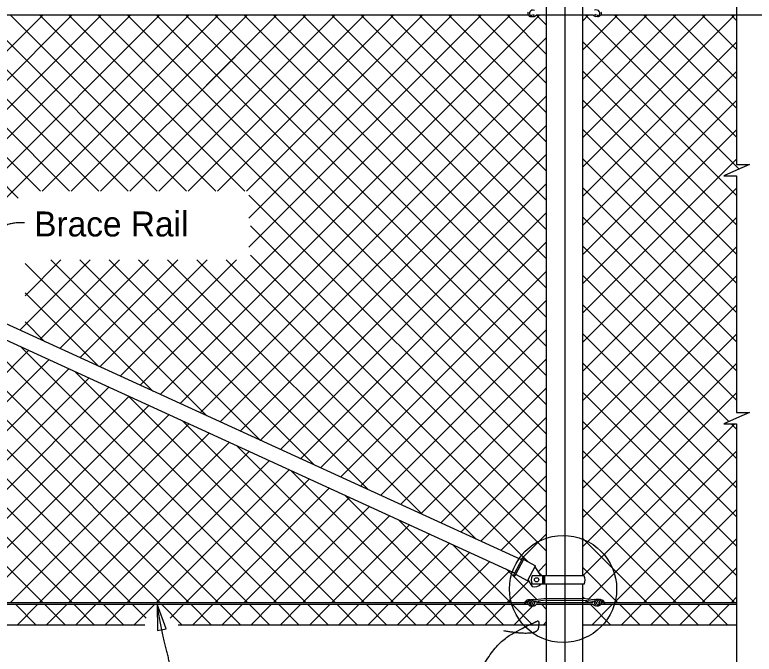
# Model space of a CAD drawing. Extents: x 0 to 41.2, y 0 to 26.
# Drawn here: x 17.77 to 23.73, y 17.23 to 22.39 of the extents above; entities that cross this region are included whole.
import ezdxf

# ---------------------------------------------------------------- set-up
doc = ezdxf.new("R2010")
doc.units = 0
for name, color, linetype in [('CL_Major', 7, 'Continuous'), ('Dimension', 7, 'Continuous'), ('Miscellaneous', 7, 'Continuous'), ('SteelMisc', 7, 'Continuous'), ('SteelMisc_h', 7, 'Continuous'), ('SupstrConc', 7, 'Continuous'), ('TextStructures', 7, 'Continuous')]:
    doc.layers.add(name, color=color, linetype=linetype)

msp = doc.modelspace()

# ---------------------------------------------------------------- linework, layer by layer
at = {"layer": 'CL_Major'}
msp.add_line((22.2062, 25.6784), (22.2062, 14.8312), dxfattribs=at)
at = {"layer": 'Dimension'}
for points in [[(23.5932, 24.349), (23.5932, 21.1819), (23.6966, 21.1819), (23.5932, 21.1369), (23.4899, 21.0919), (23.5932, 21.0919), (23.5932, 20.1983)], [(23.5932, 20.1983), (23.5932, 19.1806), (23.6966, 19.1806), (23.5932, 19.1356), (23.4899, 19.0906), (23.5932, 19.0906), (23.5932, 16.8862)]]:
    msp.add_lwpolyline(points, dxfattribs=at)
msp.add_lwpolyline([(18.9209, 17.6338), (18.9225, 17.4226), (18.992, 17.4349)], close=True, dxfattribs=at)
msp.add_circle((22.1934, 17.7574), 0.4318, dxfattribs=at)
for points in [[(17.8509, 20.7118), (17.6943, 20.72), (17.5763, 20.5615), (17.5733, 20.4403), (17.578, 20.2726), (17.6407, 19.9238)], [(18.6095, 16.8868), (18.8324, 16.8833), (18.9173, 16.9222), (19.0482, 17.0709), (18.9633, 17.3684), (18.9208, 17.6337)], [(20.4632, 14.9843), (21.3717, 14.9643), (21.3652, 16.4454), (21.4405, 16.9433), (21.6515, 17.3204), (21.8903, 17.4554), (21.9647, 17.4872), (22.0043, 17.5089), (21.982, 17.3708), (21.7151, 17.4193)]]:
    msp.add_open_spline(points, degree=2, dxfattribs=at)
at = {"layer": 'Miscellaneous'}
for p, q in [((16.1953, 20.586), (17.9993, 22.39)), ((16.32, 22.39), (17.7983, 20.9117)), ((16.357, 20.5119), (18.235, 22.39)), ((16.5186, 20.4379), (18.4707, 22.39)), ((16.5557, 22.39), (17.9778, 20.9679)), ((16.6803, 20.3639), (18.7064, 22.39)), ((16.7914, 22.39), (18.2135, 20.9679)), ((16.8419, 20.2898), (18.9421, 22.39)), ((17.0271, 22.39), (18.4492, 20.9679)), ((17.2628, 22.39), (18.6849, 20.9679)), ((17.4985, 22.39), (18.9206, 20.9679)), ((17.679, 20.8912), (19.1778, 22.39)), ((17.7342, 22.39), (19.1563, 20.9679)), ((17.9699, 22.39), (19.392, 20.9679)), ((17.9914, 20.9679), (19.4135, 22.39)), ((18.2056, 22.39), (19.6277, 20.9679)), ((18.2272, 20.9679), (19.6492, 22.39)), ((18.4413, 22.39), (22.0604, 18.7709)), ((18.677, 22.39), (22.0604, 19.0066)), ((18.6986, 20.9679), (20.1206, 22.39)), ((18.7818, 19.4013), (21.7706, 22.39)), ((18.9127, 22.39), (22.0604, 19.2423)), ((18.9343, 20.9679), (20.3563, 22.39)), ((18.9435, 19.3272), (22.0063, 22.39)), ((19.1484, 22.39), (22.0604, 19.478)), ((19.17, 20.9679), (20.5921, 22.39)), ((19.3184, 21.8234), (19.8849, 22.39)), ((19.3841, 22.39), (22.0604, 19.7137)), ((19.4057, 20.9679), (20.8278, 22.39)), ((19.6198, 22.39), (22.0604, 19.9494)), ((19.6414, 20.9679), (21.0635, 22.39)), ((19.66, 20.7508), (21.2992, 22.39)), ((19.66, 20.5151), (21.5349, 22.39)), ((19.8555, 22.39), (22.0604, 20.1851)), ((20.0912, 22.39), (22.0604, 20.4208)), ((20.3269, 22.39), (22.0604, 20.6565)), ((20.5626, 22.39), (22.0604, 20.8922)), ((20.7983, 22.39), (22.0604, 21.1279)), ((21.034, 22.39), (22.0604, 21.3636)), ((21.2697, 22.39), (22.0604, 21.5993)), ((21.5054, 22.39), (22.0604, 21.835)), ((21.7411, 22.39), (22.0604, 22.0707)), ((21.9768, 22.39), (22.0604, 22.3064)), ((22.3521, 21.3996), (23.3424, 22.39)), ((22.3521, 21.6353), (23.1067, 22.39)), ((22.3521, 21.1639), (23.5781, 22.39)), ((22.3521, 21.871), (22.871, 22.39)), ((22.3521, 22.3424), (22.3996, 22.39)), ((22.3565, 22.1112), (22.6353, 22.39)), ((22.3702, 22.39), (23.6142, 21.146)), ((22.6059, 22.39), (23.5931, 21.4028)), ((22.8416, 22.39), (23.5931, 21.6385)), ((23.0773, 22.39), (23.5931, 21.8742)), ((23.313, 22.39), (23.5931, 22.1099)), ((23.5487, 22.39), (23.5931, 22.3456)), ((19.1051, 19.2532), (22.0604, 22.2084)), ((22.3521, 22.1725), (23.5931, 20.9314)), ((22.3521, 20.9282), (23.5931, 22.1693)), ((18.4629, 20.9679), (19.5478, 22.0528)), ((19.2668, 19.1791), (22.0604, 21.9727)), ((22.3521, 21.9368), (23.5931, 20.6957)), ((22.3521, 20.6925), (23.5931, 21.9336)), ((19.4285, 19.1051), (22.0604, 21.737)), ((22.3521, 21.701), (23.5931, 20.46)), ((22.3521, 20.4568), (23.5931, 21.6979)), ((19.5901, 19.0311), (22.0604, 21.5013)), ((22.3521, 21.4653), (23.5931, 20.2243)), ((22.3521, 20.2211), (23.5931, 21.4622)), ((19.7518, 18.957), (22.0604, 21.2656)), ((22.3521, 21.2296), (23.5931, 19.9886)), ((22.3521, 19.9854), (23.5931, 21.2265)), ((19.9134, 18.883), (22.0604, 21.0299)), ((22.3521, 20.9939), (23.5931, 19.7529)), ((19.66, 20.9356), (22.0604, 18.5352)), ((22.3521, 19.7497), (23.5931, 20.9908)), ((15.2134, 20.9039), (18.4687, 17.6486)), ((20.0751, 18.8089), (22.0604, 20.7942)), ((22.3521, 20.7582), (23.5931, 19.5171)), ((22.3521, 19.514), (23.5931, 20.7551)), ((15.6483, 20.7047), (18.7044, 17.6486)), ((19.6731, 20.6868), (22.0604, 18.2995)), ((20.2368, 18.7349), (22.0604, 20.5585)), ((22.3521, 20.5225), (23.5931, 19.2814)), ((22.3521, 19.2783), (23.5931, 20.5194)), ((16.0832, 20.5055), (18.9401, 17.6486)), ((17.8119, 19.8455), (18.3797, 20.4134)), ((17.8545, 20.1239), (18.144, 20.4134)), ((17.9735, 19.7715), (18.6154, 20.4134)), ((18.0609, 20.4134), (19.3191, 19.1552)), ((18.1352, 19.6975), (18.8511, 20.4134)), ((18.2966, 20.4134), (19.754, 18.956)), ((18.2969, 19.6234), (19.0868, 20.4134)), ((18.4585, 19.5494), (19.3225, 20.4134)), ((18.5323, 20.4134), (20.1889, 18.7568)), ((18.6202, 19.4753), (19.5582, 20.4134)), ((18.768, 20.4134), (20.6238, 18.5576)), ((19.0037, 20.4134), (21.0587, 18.3584)), ((19.2394, 20.4134), (21.4936, 18.1592)), ((19.4751, 20.4134), (21.9144, 17.9741)), ((19.6731, 20.4511), (22.0604, 18.0638)), ((17.8545, 20.3841), (18.8842, 19.3544)), ((16.5181, 20.3063), (19.1758, 17.6486)), ((20.3984, 18.6608), (22.0604, 20.3228)), ((22.3521, 20.2868), (23.5306, 19.1083)), ((22.3521, 19.0426), (23.5931, 20.2837)), ((16.953, 20.1071), (19.4115, 17.6486)), ((17.8545, 20.1484), (18.4493, 19.5536)), ((20.5601, 18.5868), (22.0604, 20.0871)), ((22.3521, 20.0511), (23.5931, 18.81)), ((22.3521, 18.8069), (23.5931, 20.048)), ((17.3879, 19.9079), (19.6472, 17.6486)), ((17.8545, 19.9127), (18.0144, 19.7528)), ((20.7217, 18.5127), (22.0604, 19.8514)), ((22.3521, 19.8154), (23.5931, 18.5743)), ((22.3521, 18.5712), (23.5931, 19.8123)), ((16.6339, 18.4318), (17.8831, 19.6811)), ((17.8228, 19.7087), (19.8829, 17.6486)), ((16.2952, 19.5864), (18.233, 17.6486)), ((16.6339, 18.1961), (18.0448, 19.607)), ((20.8834, 18.4387), (22.0604, 19.6157)), ((22.3521, 19.5797), (23.5931, 18.3386)), ((22.3521, 18.3355), (23.5931, 19.5766)), ((16.6339, 17.9604), (18.2064, 19.533)), ((18.2576, 19.5095), (20.1186, 17.6486)), ((16.5577, 17.6486), (18.3681, 19.4589)), ((16.2349, 19.4109), (17.9973, 17.6486)), ((16.7934, 17.6486), (18.5298, 19.3849)), ((21.045, 18.3647), (22.0604, 19.38)), ((22.3521, 19.344), (23.5931, 18.1029)), ((22.3521, 18.0998), (23.5931, 19.3409)), ((17.0291, 17.6486), (18.6914, 19.3109)), ((18.6925, 19.3103), (20.3543, 17.6486)), ((17.2648, 17.6486), (18.8531, 19.2368)), ((17.5005, 17.6486), (19.0147, 19.1628)), ((21.2067, 18.2906), (22.0604, 19.1443)), ((17.7362, 17.6486), (19.1764, 19.0887)), ((19.1274, 19.1111), (20.59, 17.6486)), ((22.3521, 19.1083), (23.5931, 17.8672)), ((22.3521, 17.8641), (23.5785, 19.0905)), ((23.5484, 19.0905), (23.5931, 19.0457)), ((17.9719, 17.6486), (19.338, 19.0147)), ((18.2076, 17.6486), (19.4997, 18.9406)), ((19.5623, 18.912), (20.8257, 17.6486)), ((21.3684, 18.2166), (22.0604, 18.9086)), ((18.4433, 17.6486), (19.6614, 18.8666)), ((22.3521, 18.8726), (23.5761, 17.6486)), ((22.4004, 17.6767), (23.5931, 18.8695)), ((18.679, 17.6486), (19.823, 18.7926)), ((18.9147, 17.6486), (19.9847, 18.7185)), ((19.9972, 18.7128), (21.0614, 17.6486)), ((21.53, 18.1425), (22.0604, 18.6729)), ((19.1504, 17.6486), (20.1463, 18.6445)), ((22.3521, 18.6369), (23.3404, 17.6486)), ((22.6079, 17.6486), (23.5931, 18.6338)), ((19.3861, 17.6486), (20.308, 18.5704)), ((19.6218, 17.6486), (20.4697, 18.4964)), ((20.4321, 18.5136), (21.2971, 17.6486)), ((21.6917, 18.0685), (22.0604, 18.4372)), ((19.8575, 17.6486), (20.6313, 18.4223)), ((22.3521, 18.4012), (23.1047, 17.6486)), ((22.8436, 17.6486), (23.5931, 18.3981)), ((20.0932, 17.6486), (20.793, 18.3483)), ((20.867, 18.3144), (21.5328, 17.6486)), ((20.3289, 17.6486), (20.9546, 18.2742)), ((20.5646, 17.6486), (21.1163, 18.2002)), ((21.8533, 17.9944), (22.0604, 18.2015)), ((22.3521, 18.1655), (22.869, 17.6486)), ((23.0793, 17.6486), (23.5931, 18.1624)), ((20.8003, 17.6486), (21.278, 18.1262)), ((21.3019, 18.1152), (21.7685, 17.6486)), ((21.0361, 17.6486), (21.4396, 18.0521)), ((21.2718, 17.6486), (21.6013, 17.9781)), ((21.9916, 17.897), (22.0604, 17.9658)), ((21.5075, 17.6486), (21.7629, 17.904)), ((21.7368, 17.916), (21.9815, 17.6713)), ((21.9917, 17.8968), (22.0239, 17.8646)), ((22.3521, 17.9298), (22.6333, 17.6486)), ((23.315, 17.6486), (23.5931, 17.9267)), ((21.7432, 17.6486), (21.9158, 17.8212)), ((21.8835, 17.6486), (21.8871, 17.6521)), ((21.9931, 17.6597), (22.0042, 17.6486)), ((22.3521, 17.6941), (22.365, 17.6812)), ((22.3722, 17.6486), (22.3882, 17.6645)), ((22.3809, 17.6653), (22.3976, 17.6486)), ((22.3929, 17.6692), (22.397, 17.6733)), ((23.5507, 17.6486), (23.5931, 17.691)), ((17.7763, 17.6338), (17.9408, 17.4693)), ((17.7927, 17.4693), (17.9572, 17.6338)), ((18.012, 17.6338), (18.1765, 17.4693)), ((18.0284, 17.4693), (18.1929, 17.6338)), ((18.2478, 17.6338), (18.4122, 17.4693)), ((18.2641, 17.4693), (18.4286, 17.6338)), ((18.4835, 17.6338), (18.6479, 17.4693)), ((18.4998, 17.4693), (18.6643, 17.6338)), ((18.7192, 17.6338), (18.8307, 17.5223)), ((18.7355, 17.4693), (18.9, 17.6338)), ((18.9549, 17.6338), (19.1193, 17.4693)), ((19.0244, 17.5226), (19.1357, 17.6338)), ((19.1906, 17.6338), (19.355, 17.4693)), ((19.2069, 17.4693), (19.3714, 17.6338)), ((19.4263, 17.6338), (19.5907, 17.4693)), ((19.4426, 17.4693), (19.6071, 17.6338)), ((19.662, 17.6338), (19.8264, 17.4693)), ((19.6783, 17.4693), (19.8428, 17.6338)), ((19.8977, 17.6338), (20.0621, 17.4693)), ((19.914, 17.4693), (20.0785, 17.6338)), ((20.1334, 17.6338), (20.2978, 17.4693)), ((20.1497, 17.4693), (20.3142, 17.6338)), ((20.3691, 17.6338), (20.5336, 17.4693)), ((20.3854, 17.4693), (20.5499, 17.6338)), ((20.6048, 17.6338), (20.7693, 17.4693)), ((20.6211, 17.4693), (20.7856, 17.6338)), ((20.8405, 17.6338), (21.005, 17.4693)), ((20.8568, 17.4693), (21.0213, 17.6338)), ((21.0762, 17.6338), (21.2407, 17.4693)), ((21.0925, 17.4693), (21.257, 17.6338)), ((21.3119, 17.6338), (21.4764, 17.4693)), ((21.3282, 17.4693), (21.4927, 17.6338)), ((21.5476, 17.6338), (21.7121, 17.4693)), ((21.5639, 17.4693), (21.7284, 17.6338)), ((21.7833, 17.6338), (21.9478, 17.4693)), ((21.7996, 17.4693), (21.9506, 17.6203)), ((22.019, 17.6338), (22.0604, 17.5924)), ((22.3521, 17.6284), (22.3575, 17.6338)), ((22.4124, 17.6338), (22.5768, 17.4693)), ((22.4287, 17.4693), (22.5932, 17.6338)), ((22.6481, 17.6338), (22.8125, 17.4693)), ((22.6644, 17.4693), (22.8289, 17.6338)), ((22.8838, 17.6338), (23.0482, 17.4693)), ((22.9001, 17.4693), (23.0646, 17.6338)), ((23.1195, 17.6338), (23.2839, 17.4693)), ((23.1358, 17.4693), (23.3003, 17.6338)), ((23.3552, 17.6338), (23.5196, 17.4693)), ((23.3715, 17.4693), (23.536, 17.6338)), ((23.5909, 17.6338), (23.5931, 17.6315)), ((22.0353, 17.4693), (22.0604, 17.4944))]:
    msp.add_line(p, q, dxfattribs=at)
at = {"layer": 'SteelMisc'}
for p, q in [((22.0604, 17.8646), (22.0604, 24.349)), ((22.3521, 17.8646), (22.3521, 24.349)), ((12.4978, 22.39), (21.9118, 22.39)), ((21.9767, 22.39), (22.0603, 22.39)), ((22.352, 22.39), (22.4351, 22.39)), ((22.4978, 22.39), (25.9375, 22.39)), ((21.8588, 17.9919), (12.6088, 22.2288)), ((21.8028, 17.8858), (12.5526, 22.1225)), ((21.7953, 17.8717), (21.8678, 18.0088)), ((21.8072, 17.8654), (21.8796, 18.0026)), ((21.8755, 17.9947), (21.9698, 17.9448)), ((21.9061, 17.8242), (21.9698, 17.9448)), ((21.9656, 17.9368), (22.0124, 17.8651)), ((21.9061, 17.8242), (21.8118, 17.8741)), ((21.9095, 17.8308), (21.9443, 17.7777)), ((22.3634, 17.8646), (21.9436, 17.8646)), ((22.026, 17.8584), (22.0495, 17.8584)), ((22.026, 17.8486), (22.0495, 17.8486)), ((22.026, 17.8368), (22.0495, 17.8368)), ((22.3633, 17.7968), (21.9436, 17.7968)), ((22.026, 17.825), (22.0495, 17.825)), ((22.026, 17.8142), (22.0495, 17.8142)), ((22.026, 17.8046), (22.0495, 17.8046)), ((22.0604, 17.0944), (22.0604, 17.7968)), ((22.3521, 17.0944), (22.3521, 17.7968)), ((22.0604, 17.6812), (21.9675, 17.6695)), ((22.0604, 17.6667), (21.9676, 17.657)), ((22.0604, 17.6812), (22.3516, 17.6829)), ((22.0604, 17.6667), (22.3516, 17.6683)), ((22.3516, 17.6829), (22.4435, 17.6713)), ((22.3516, 17.6683), (22.4434, 17.6588)), ((12.5141, 17.6338), (21.9119, 17.6338)), ((12.5154, 17.6486), (21.8852, 17.6486)), ((21.8952, 17.6486), (21.9083, 17.6486)), ((21.9768, 17.6338), (22.0604, 17.6338)), ((21.9782, 17.6486), (22.0604, 17.6486)), ((22.3521, 17.6486), (22.4325, 17.6486)), ((22.3521, 17.6338), (22.4351, 17.6338)), ((22.4979, 17.6338), (23.5931, 17.6338)), ((22.5028, 17.6486), (22.518, 17.6486)), ((22.5265, 17.6486), (23.5931, 17.6486))]:
    msp.add_line(p, q, dxfattribs=at)
for centre, start, end in [((21.8739, 18.0058), 332.14902, 152.14902), ((21.8014, 17.8686), 152.14902, 332.14902)]:
    msp.add_arc(centre, 0.00673, start, end, dxfattribs=at)
for centre, major_axis, ratio, start_param, end_param in [((21.9507, 22.3996), (0.0295, 0), 0.957868, 1.132635, 3.996184), ((22.4603, 22.4014), (-0.0295, 0), 0.957868, 2.287002, 5.15055), ((21.9331, 22.4025), (-0.0249, 0), 0.957868, 5.913851, 7.104804), ((21.9344, 22.3985), (0.0231, 0), 0.957868, 3.795406, 4.839145), ((21.9405, 22.3928), (0.0206, -0.0021), 0.798607, 4.329004, 5.170153), ((21.954, 22.3928), (0.0206, -0.0021), 0.798607, 3.319436, 5.220153), ((21.9552, 22.3949), (-0.00795, 0), 0.957868, 0.039428, 2.999692), ((21.9466, 22.4115), (0.0391, 0), 0.957868, 5.134108, 5.41974), ((21.9537, 22.3995), (0.0251, 0), 0.957868, 5.531357, 5.877802), ((22.4572, 22.4013), (-0.0251, 0), 0.957868, 0.487549, 0.751829), ((22.4643, 22.4133), (-0.0391, 0), 0.957868, 0.863445, 1.149078), ((22.4558, 22.3967), (0.00795, 0), 0.957868, 3.283494, 6.243757), ((22.4569, 22.3945), (-0.0206, -0.0021), 0.798607, 1.063032, 2.96375), ((22.4704, 22.3945), (-0.0206, -0.0021), 0.798607, 1.113032, 1.956656), ((22.4765, 22.4002), (-0.0231, 0), 0.957868, 1.44404, 2.503632), ((22.4779, 22.4042), (0.0249, 0), 0.957868, 5.476514, 6.65252), ((22.0129, 17.8309), (-0.0776, 0), 0.957868, 5.810211, 6.75616), ((22.2943, 17.8309), (0.0776, 0), 0.957868, 5.807767, 6.754779), ((21.9609, 17.846), (0.0647, -0.0342), 0.957868, 4.95193, 6.011789), ((21.9195, 17.6343), (0.0373, 0), 0.957868, 1.427863, 3.108042), ((21.9406, 17.5946), (-0.0724, 0), 0.957868, 5.133134, 5.652106), ((21.9331, 17.6463), (-0.0249, 0), 0.957868, 5.913851, 7.104804), ((21.932, 17.6488), (0.023, 0), 0.957868, 1.234085, 2.861055), ((21.9507, 17.6434), (0.0295, 0), 0.957868, 1.132635, 3.996184), ((21.9642, 17.6452), (-0.0303, -0.0108), 0.724765, 4.35367, 6.224248), ((21.9693, 17.6323), (-0.0259, 0), 0.957868, 4.777514, 5.646371), ((21.9535, 17.6445), (0.0119, 0), 0.957868, 5.725876, 7.416677), ((21.9538, 17.6433), (0.0251, 0), 0.957868, 0.221743, 0.642584), ((22.4573, 17.6451), (-0.0251, 0), 0.957868, 5.640694, 6.136824), ((22.4418, 17.634), (0.0259, 0), 0.957868, 0.636815, 1.505671), ((22.4468, 17.647), (0.0303, -0.0108), 0.724765, 0.058937, 1.929515), ((22.4575, 17.6463), (-0.0119, 0), 0.957868, 5.149694, 6.840495), ((22.4603, 17.6452), (-0.0295, 0), 0.957868, 2.287002, 5.15055), ((22.479, 17.6505), (-0.023, 0), 0.957868, 3.422131, 5.0491), ((22.4915, 17.6361), (-0.0373, 0), 0.957868, 3.175144, 4.855322), ((22.4779, 17.648), (0.0249, 0), 0.957868, 5.461566, 6.65252), ((22.4704, 17.5964), (0.0724, 0), 0.957868, 0.631079, 1.150052), ((21.9345, 17.6423), (0.0231, 0), 0.957868, 3.795406, 4.839145), ((21.9406, 17.6366), (0.0206, -0.0021), 0.798607, 4.32653, 5.170153), ((21.9541, 17.6366), (0.0206, -0.0021), 0.798607, 3.319436, 5.220153), ((21.9609, 17.6411), (-0.0139, 0), 0.957868, 5.822914, 6.485782), ((21.9552, 17.6387), (-0.00795, 0), 0.957868, 0.039428, 2.999692), ((21.9467, 17.6553), (0.0391, 0), 0.957868, 5.134108, 5.41974), ((21.9535, 17.6445), (0.0119, 0), 0.957868, 5.639684, 5.725876), ((21.9538, 17.6433), (0.0251, 0), 0.957868, 5.531357, 5.877802), ((22.4573, 17.6451), (-0.0251, 0), 0.957868, 0.487549, 0.751829), ((22.4643, 17.6571), (-0.0391, 0), 0.957868, 0.863445, 1.149078), ((22.4575, 17.6463), (-0.0119, 0), 0.957868, 0.557309, 0.643501), ((22.4558, 17.6405), (0.00795, 0), 0.957868, 3.283494, 6.243757), ((22.4569, 17.6383), (-0.0206, -0.0021), 0.798607, 1.063032, 2.96375), ((22.4501, 17.6429), (0.0139, 0), 0.957868, 6.080589, 6.743456), ((22.4704, 17.6383), (-0.0206, -0.0021), 0.798607, 1.113032, 1.956656), ((22.4765, 17.644), (-0.0231, 0), 0.957868, 1.44404, 2.487779)]:
    msp.add_ellipse(centre, major_axis=major_axis, ratio=ratio, start_param=start_param, end_param=end_param, dxfattribs=at)
msp.add_ellipse((21.9795, 17.8313), major_axis=(0.0178, 0), ratio=0.957868, dxfattribs=at)
at = {"layer": 'SteelMisc_h'}
for p, q in [((22.0603, 22.39), (22.352, 22.39)), ((22.0604, 17.6486), (22.3521, 17.6486)), ((22.0604, 17.6338), (22.3521, 17.6338))]:
    msp.add_line(p, q, dxfattribs=at)
at = {"layer": 'SupstrConc'}
for p, q in [((12.3521, 17.4693), (18.8204, 17.4693)), ((19.0892, 17.4693), (22.0604, 17.4693)), ((22.3521, 17.4693), (23.5931, 17.4693))]:
    msp.add_line(p, q, dxfattribs=at)

# ---------------------------------------------------------------- texts
at = {"layer": 'TextStructures'}
msp.add_text('Brace Rail', height=0.2016, dxfattribs=at).set_placement((17.9282, 20.6019))

doc.saveas('drawing.dxf')
